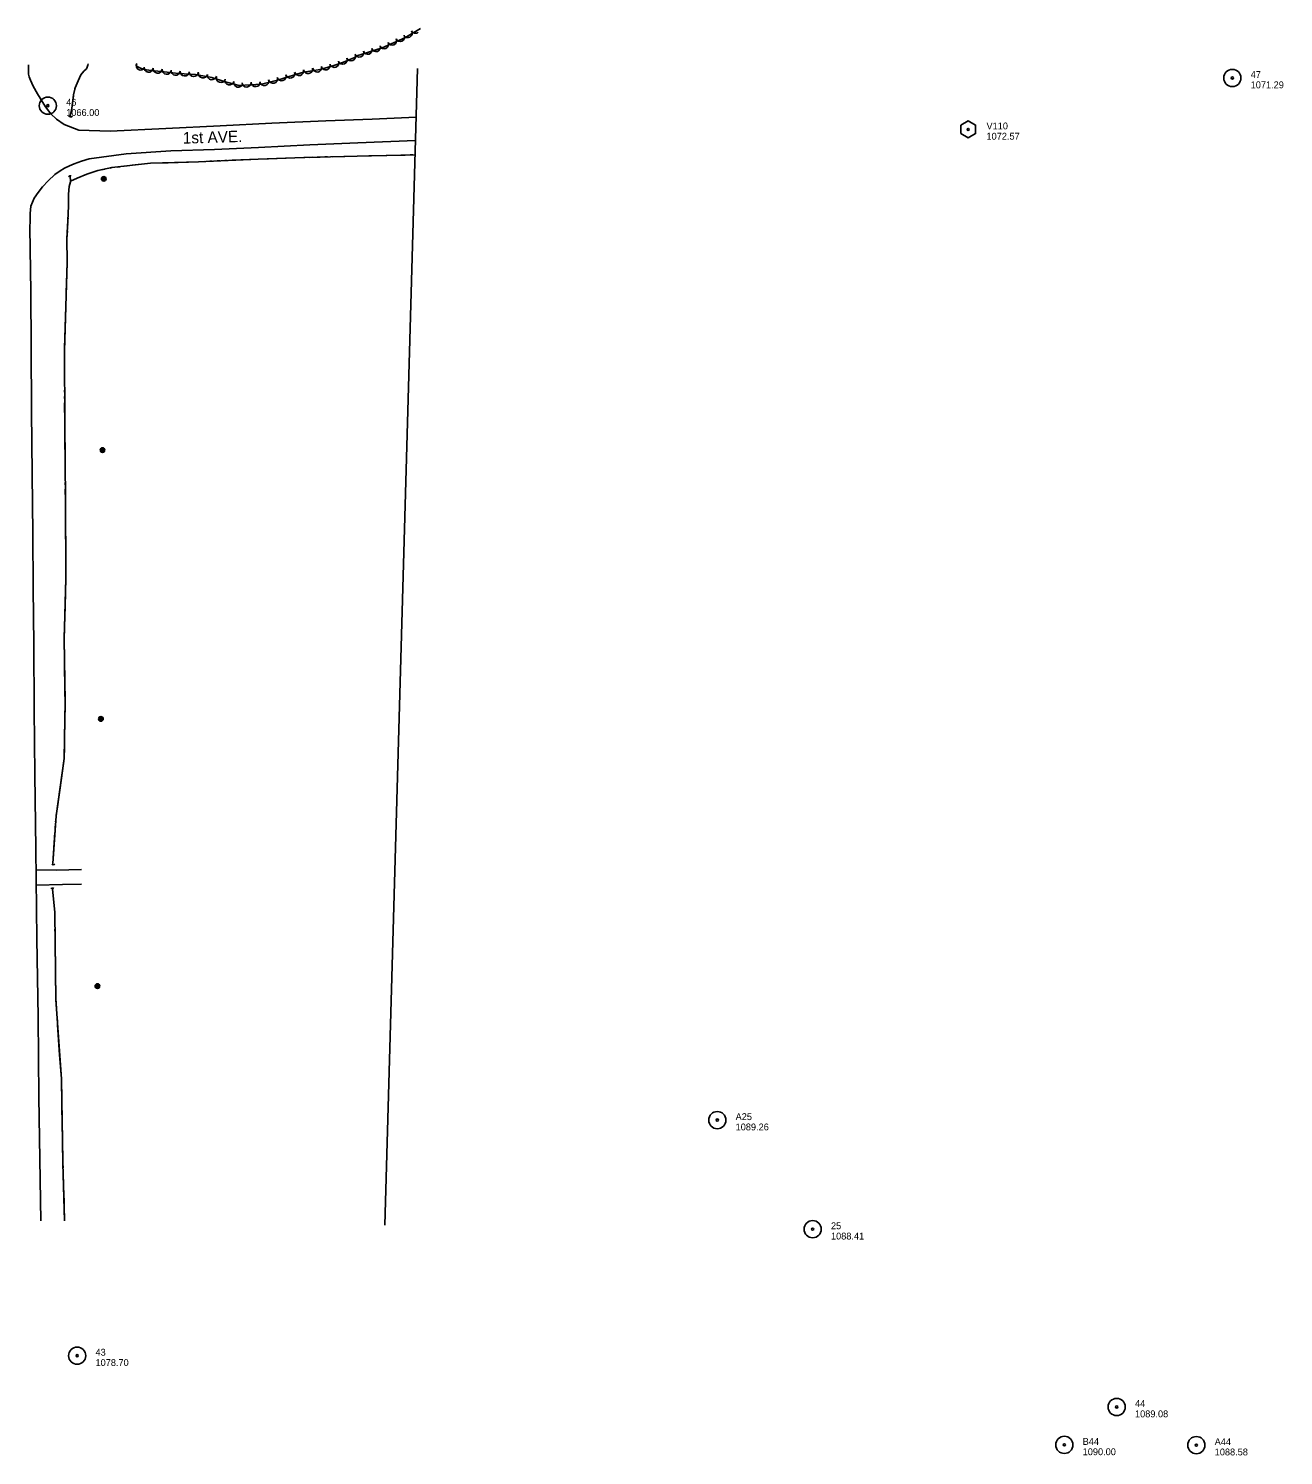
# Model space of a CAD drawing. Extents: x 296487 to 298842, y 31545 to 32791.
# Drawn here: x 297746 to 298842, y 31545 to 32791 of the extents above; entities that cross this region are included whole.
import ezdxf

# ---------------------------------------------------------------- set-up
doc = ezdxf.new("R2010")
doc.units = 0
for name, color, linetype in [('Level 11', 7, 'Continuous'), ('Level 14', 7, 'Continuous'), ('Level 15', 7, 'Continuous'), ('Level 17', 7, 'Continuous'), ('Level 18', 7, 'Continuous'), ('Level 19', 7, 'Continuous'), ('Level 4', 7, 'Continuous'), ('Level 5', 7, 'Continuous'), ('Level 6', 7, 'Continuous')]:
    doc.layers.add(name, color=color, linetype=linetype)

msp = doc.modelspace()

# ---------------------------------------------------------------- linework, layer by layer
at = {"layer": 'Level 11'}
for points in [[(298084.2, 32713.7), (298045.7, 32712.1), (298005.3, 32710.5), (297958.2, 32708.5), (297913.2, 32706.2), (297865.7, 32703.8), (297817.1, 32701.5), (297789.7, 32702.4), (297776.8, 32707.5), (297770.2, 32712.1), (297765.3, 32716.7), (297760.6, 32722.8), (297753.6, 32734), (297749.9, 32740.9), (297747.5, 32746), (297746.3, 32748.9), (297745.8, 32751.4), (297745.7, 32759.5)], [(297756.5, 31749.8), (297754.8, 31857.8), (297754.1, 31927.5), (297753, 31995.9), (297752.2, 32074.7), (297751.3, 32139.7), (297750.7, 32196.6), (297750.3, 32253), (297749.8, 32302.4), (297749.5, 32350.2), (297749, 32402), (297748.4, 32456.9), (297748.1, 32513.1), (297747.8, 32561.2), (297746.8, 32617.5), (297747, 32623.2), (297747.2, 32629.5), (297747.6, 32636), (297750.7, 32643.1), (297754.2, 32648), (297757.8, 32653), (297763, 32658.2), (297768.8, 32663.7), (297773.3, 32666.9), (297777.2, 32669.3), (297781.5, 32671.3), (297785.6, 32673.1), (297788.8, 32674.3), (297792.1, 32675.3), (297798.7, 32677.5), (297831.1, 32681.7), (297869.9, 32684.3), (297908, 32685.4), (297946.4, 32687.3), (297991.4, 32689.6), (298033.2, 32691.2), (298083.6, 32693.4)]]:
    msp.add_lwpolyline(points, dxfattribs=at)
at = {"layer": 'Level 14'}
for centre, radius in [((297811.4, 32659.9), 2.02), ((297811.4, 32659.9), 1.52), ((297811.4, 32659.9), 1.01), ((297811.4, 32660), 0.502), ((297810.3, 32423), 2.02), ((297810.2, 32423), 1.52), ((297810.3, 32423), 1.01), ((297810.3, 32423), 0.502), ((297808.9, 32188.1), 2.02), ((297808.9, 32188.1), 1.52), ((297808.9, 32188.1), 1.01), ((297808.9, 32188.1), 0.502), ((297805.9, 31954.8), 2.02), ((297805.9, 31954.8), 1.52), ((297805.9, 31954.8), 1.01), ((297805.9, 31954.8), 0.502)]:
    msp.add_circle(centre, radius, dxfattribs=at)
at = {"layer": 'Level 15'}
for centre, radius, start, end in [((297782.5, 32716.2), 2.27, 210.0819, 316.3214), ((297782, 32661), 1.48, 49.4502, 155.6897), ((297767.3, 32062.3), 1.6, 216.656, 322.8955), ((297766.6, 32039), 1.41, 40.8674, 147.107)]:
    msp.add_arc(centre, radius, start, end, dxfattribs=at)
at = {"layer": 'Level 17'}
for points in [[(297792.1, 32056.5), (297769.7, 32055.9), (297752.4, 32056.2)], [(297752.5, 32043), (297775.5, 32043.6), (297792, 32043.9)]]:
    msp.add_lwpolyline(points, dxfattribs=at)
at = {"layer": 'Level 18'}
for points in [[(298031.6, 32767), (298054.4, 32774.4), (298074.2, 32783.2), (298087.9, 32791.2)], [(297839.6, 32759.3), (297840.6, 32758.1), (297843.4, 32756.5), (297848.3, 32755.2), (297853, 32754.6), (297858.7, 32754), (297866.9, 32753.1), (297876.6, 32752), (297891.4, 32751), (297905.8, 32748.3), (297916.6, 32744.9), (297929.8, 32741.5), (297949.1, 32742.6), (297963.2, 32746.2), (297973.2, 32749.3), (297985.7, 32753), (298000.3, 32755.4), (298012.3, 32758.9), (298020.7, 32761.9), (298031.9, 32766.5)]]:
    msp.add_lwpolyline(points, dxfattribs=at)
for centre, radius, start, end in [((298063.3, 32780.6), 3.85, 203.9249, 23.9096), ((298070.3, 32783.7), 3.85, 203.9249, 23.9096), ((298076.9, 32787.1), 3.85, 210.1735, 30.1582), ((298083.6, 32791), 3.85, 210.1735, 309.0788), ((298027.4, 32766.9), 3.97, 202.1447, 22.1294), ((298034.6, 32770.1), 3.85, 197.9516, 17.9363), ((298041.9, 32772.5), 3.85, 197.9516, 17.9363), ((298049.2, 32774.9), 3.85, 197.9516, 17.9363), ((298056.3, 32777.4), 3.85, 203.9249, 23.9096), ((297843.7, 32758.8), 3.97, 150.7141, 330.6987), ((297850.6, 32757), 3.97, 172.442, 352.4266), ((297858.5, 32756.1), 3.97, 173.6244, 353.6091), ((297989.9, 32755.8), 3.97, 189.439, 9.4236), ((297997.8, 32757.1), 3.97, 189.439, 9.4236), ((298005.2, 32759), 3.97, 196.1377, 16.1224), ((298012.7, 32761.2), 3.97, 200.1017, 20.0864), ((298020.1, 32763.9), 3.97, 202.1447, 22.1294), ((297866.4, 32755.2), 3.97, 173.7835, 353.7681), ((297874.2, 32754.3), 3.97, 173.6097, 353.5944), ((297882.1, 32753.7), 3.97, 176.2287, 356.2133), ((297890, 32753.2), 3.97, 176.2287, 356.2133), ((297898.1, 32751.9), 3.97, 169.4047, 349.3894), ((297905.9, 32750.4), 3.97, 169.4047, 349.3894), ((297913.7, 32748), 3.97, 162.334, 342.3187), ((297921.2, 32745.9), 3.97, 165.8125, 345.7971), ((297928.9, 32743.9), 3.97, 165.8125, 345.7971), ((297936.1, 32744), 3.97, 183.0249, 3.0096), ((297944.1, 32744.4), 3.97, 183.0249, 3.0096), ((297951.5, 32745.3), 3.97, 194.5787, 14.5633), ((297959.2, 32747.3), 3.97, 194.5787, 14.5633), ((297966.7, 32749.5), 3.97, 197.3731, 17.3578), ((297974.3, 32751.8), 3.97, 196.1644, 16.149), ((297982, 32754.1), 3.97, 196.1644, 16.149)]:
    msp.add_arc(centre, radius, start, end, dxfattribs=at)
at = {"layer": 'Level 19'}
for points in [[(297782.1, 32714.7), (297783.4, 32721.5), (297785.1, 32733.4), (297786.3, 32739.3), (297789, 32745.5), (297791.4, 32750.6), (297794.1, 32753.8), (297796.2, 32756), (297797, 32757.5), (297797.5, 32759.1), (297797.8, 32760.3)], [(297788.9, 32745.2), (297789, 32745.5), (297791.4, 32750.6), (297794.1, 32753.8), (297796.2, 32756), (297797, 32757.5), (297797.5, 32759.1), (297797.8, 32760.3)], [(297782.1, 32714.7), (297783.4, 32721.5), (297785, 32732.3)], [(297785.4, 32734.8), (297785.7, 32736)], [(297786.2, 32738.4), (297786.3, 32739.3), (297786.4, 32739.6)], [(297787.4, 32741.8), (297787.9, 32743)], [(297782.5, 32657.8), (297788.1, 32660.4), (297796.5, 32664), (297806.2, 32667.2), (297818.6, 32669.7), (297852.2, 32673.6), (297894.1, 32674.7), (297946.2, 32677.1), (297986, 32678.4), (298032.8, 32679.8), (298083.3, 32680.9)], [(297816.6, 32669.3), (297818.6, 32669.7), (297818.7, 32669.7)], [(297823.1, 32670.2), (297825.3, 32670.5)], [(297829.6, 32671), (297831.8, 32671.2)], [(297836.1, 32671.7), (297852.2, 32673.6), (297867.8, 32674)], [(297867.8, 32674), (297894.1, 32674.7), (297899.6, 32675)], [(297903.9, 32675.2), (297906.1, 32675.3)], [(297910.5, 32675.5), (297912.7, 32675.6)], [(297917.1, 32675.8), (297919.3, 32675.9)], [(297923.6, 32676.1), (297946.2, 32677.1), (297955.4, 32677.4)], [(297955.4, 32677.4), (297986, 32678.4), (297987.1, 32678.5)], [(297991.5, 32678.6), (297993.7, 32678.7)], [(297998.1, 32678.8), (298000.3, 32678.8)], [(298004.6, 32679), (298006.8, 32679)], [(298011.2, 32679.1), (298032.8, 32679.8), (298043, 32680)], [(298043, 32680), (298074.7, 32680.7)], [(298079.1, 32680.8), (298081.3, 32680.8)], [(297767, 32061.7), (297769.7, 32103.4), (297776.9, 32153.6), (297777.6, 32203.5), (297776.8, 32257.4), (297778.3, 32310.7), (297777.9, 32378.9), (297777.3, 32446.9), (297777, 32509.7), (297779.5, 32586.8), (297779.3, 32607.9), (297780.1, 32623.3), (297780.6, 32636.4), (297780.7, 32646.6), (297781.3, 32653.1), (297782.5, 32657.3), (297782.5, 32659.3), (297781.9, 32662.1)], [(297780.5, 32635.1), (297780.6, 32636.4), (297780.7, 32646.6), (297781.3, 32653.1), (297782.5, 32657.3), (297782.5, 32659.3), (297781.9, 32662.1)], [(297782.5, 32657.8), (297788.1, 32660.4), (297796.5, 32664), (297806.2, 32667.2), (297812.3, 32668.4)], [(297780.3, 32629.5), (297780.4, 32631.3)], [(297779.8, 32618.2), (297779.9, 32620.1)], [(297780.1, 32623.8), (297780.2, 32625.7)], [(297779.5, 32587.2), (297779.3, 32607.9), (297779.6, 32614.4)], [(297778.7, 32559.9), (297779.5, 32586.8), (297779.5, 32587.2)], [(297778.1, 32543), (297778.2, 32544.9)], [(297778.3, 32548.7), (297778.3, 32550.6)], [(297778.5, 32554.3), (297778.5, 32556.2)], [(297777.1, 32512), (297778, 32539.3)], [(297777.1, 32484.8), (297777, 32509.7), (297777.1, 32512)], [(297777.2, 32479.2), (297777.2, 32481)], [(297777.2, 32473.5), (297777.2, 32475.4)], [(297777.2, 32467.9), (297777.2, 32469.8)], [(297777.4, 32436.9), (297777.3, 32446.9), (297777.2, 32464.1)], [(297777.6, 32409.6), (297777.4, 32436.9)], [(297777.7, 32404), (297777.7, 32405.9)], [(297777.7, 32398.3), (297777.7, 32400.2)], [(297777.8, 32392.7), (297777.7, 32394.6)], [(297778, 32361.7), (297777.9, 32378.9), (297777.8, 32388.9)], [(297778.2, 32334.4), (297778, 32361.7)], [(297778.2, 32328.8), (297778.2, 32330.7)], [(297778.2, 32323.2), (297778.2, 32325)], [(297777.6, 32286.5), (297778.3, 32310.7), (297778.3, 32313.8)], [(297778.3, 32317.5), (297778.3, 32319.4)], [(297776.9, 32259.3), (297777.6, 32286.5)], [(297776.9, 32253.6), (297776.8, 32255.5)], [(297777, 32248), (297776.9, 32249.9)], [(297777, 32242.4), (297777, 32244.3)], [(297777.5, 32211.4), (297777.1, 32238.6)], [(297777.3, 32184.1), (297777.6, 32203.5), (297777.5, 32211.4)], [(297777.2, 32178.5), (297777.3, 32180.4)], [(297777.2, 32172.8), (297777.2, 32174.7)], [(297774.4, 32136.4), (297776.9, 32153.6), (297777, 32163.5)], [(297777.1, 32167.2), (297777.1, 32169.1)], [(297770.6, 32109.4), (297774.4, 32136.4)], [(297769.4, 32098.2), (297769.5, 32100.1)], [(297769.8, 32103.8), (297770, 32105.7)], [(297767, 32061.7), (297768.8, 32088.8)], [(297769, 32092.6), (297769.1, 32094.5)], [(297777, 31749.8), (297775.8, 31800.1), (297774.4, 31873.7), (297769.6, 31942.8), (297768.6, 32019.1), (297766.6, 32039.6)], [(297768.7, 32013.4), (297768.6, 32019.1), (297766.6, 32039.6)], [(297768.8, 32008), (297768.7, 32009.8)], [(297768.8, 32002.6), (297768.8, 32004.4)], [(297768.9, 31997.1), (297768.9, 31998.9)], [(297769.3, 31967.2), (297769, 31993.5)], [(297769.8, 31940.9), (297769.6, 31942.8), (297769.3, 31967.2)], [(297770.1, 31935.5), (297770, 31937.3)], [(297770.5, 31930.1), (297770.4, 31931.9)], [(297770.9, 31924.6), (297770.8, 31926.4)], [(297772.9, 31894.8), (297771.1, 31921)], [(297774.5, 31868.5), (297774.4, 31873.7), (297772.9, 31894.8)], [(297774.6, 31863.1), (297774.6, 31864.9)], [(297774.7, 31857.7), (297774.7, 31859.5)], [(297774.8, 31852.2), (297774.8, 31854)], [(297775.4, 31822.3), (297774.9, 31848.6)], [(297775.9, 31796), (297775.8, 31800.1), (297775.4, 31822.3)], [(297776.1, 31790.6), (297776, 31792.4)], [(297776.2, 31785.2), (297776.1, 31787)], [(297776.3, 31779.7), (297776.3, 31781.5)], [(297777, 31749.8), (297776.4, 31776.1)]]:
    msp.add_lwpolyline(points, dxfattribs=at)
at = {"layer": 'Level 4'}
msp.add_lwpolyline([(298056.9, 31745.8), (298085.4, 32756.4)], dxfattribs=at)
at = {"layer": 'Level 5'}
msp.add_lwpolyline([(298559.9, 32706.9), (298559.9, 32699.5), (298566.4, 32695.8), (298572.8, 32699.4), (298572.8, 32706.8), (298566.3, 32710.5)], close=True, dxfattribs=at)
msp.add_circle((298566.3, 32703.1), 0.871, dxfattribs=at)
at = {"layer": 'Level 6'}
for centre, radius in [((298797, 32748), 7.5), ((298797, 32748), 0.96), ((297762.6, 32723.8), 7.5), ((297762.6, 32723.8), 0.96), ((298347.2, 31837.7), 7.5), ((298347.2, 31837.7), 0.96), ((298430.5, 31742.4), 7.5), ((298430.5, 31742.4), 0.96), ((297788.2, 31631.9), 7.5), ((297788.2, 31631.9), 0.96), ((298696, 31587.1), 7.5), ((298696, 31587.1), 0.96), ((298650.3, 31554), 7.5), ((298765.6, 31553.8), 7.5), ((298650.3, 31554), 0.96), ((298765.6, 31553.8), 0.96)]:
    msp.add_circle(centre, radius, dxfattribs=at)

# ---------------------------------------------------------------- texts
at = {"layer": 'Level 11'}
msp.add_text('1st AVE.', height=10, rotation=1.6629, dxfattribs=at).set_placement((297880.6, 32690.6))
at = {"layer": 'Level 5'}
for s, p in [('V110', (298582.3, 32703.1)), ('1072.57', (298582.3, 32694.1))]:
    msp.add_text(s, height=6, dxfattribs=at).set_placement(p)
at = {"layer": 'Level 6'}
for s, p in [('47', (298813, 32748)), ('1071.29', (298813, 32739)), ('46', (297778.6, 32723.8)), ('1066.00', (297778.6, 32714.8)), ('A25', (298363.2, 31837.7)), ('1089.26', (298363.2, 31828.7)), ('25', (298446.5, 31742.4)), ('1088.41', (298446.5, 31733.4)), ('43', (297804.2, 31631.9)), ('1078.70', (297804.2, 31622.9)), ('44', (298712, 31587.1)), ('1089.08', (298712, 31578.1)), ('B44', (298666.3, 31554)), ('A44', (298781.6, 31553.8)), ('1090.00', (298666.3, 31545)), ('1088.58', (298781.6, 31544.8))]:
    msp.add_text(s, height=6, dxfattribs=at).set_placement(p)

doc.saveas('drawing.dxf')
